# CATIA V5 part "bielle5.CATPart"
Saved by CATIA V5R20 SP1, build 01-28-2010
Part number: bielle5
Bounding box of the stored display mesh (mm): x 1 to 9, y -99.99 to 272.465, z -199.995 to -22.535
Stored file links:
  C:\Users\Fabien-port\Desktop\test\bielle5.CATPart
  C:\Users\Fabien-port\Desktop\test\mecanisme_a_coulisseau.CATProduct
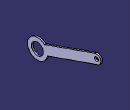
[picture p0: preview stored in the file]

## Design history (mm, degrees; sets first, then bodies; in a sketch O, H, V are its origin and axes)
External parameters (linked from other documents)
  External.largeur_bielle = 15 mm
  External.epaisseur_bielle = 8 mm
  External.cote_coulisseau = 30 mm
  External.grand_rayon_bielle5 = 50 mm
  External.rayon_cylindre_bielle = 10 mm
Set1
  Plane1 "Plan_decalage": linked copy from another document
  Point1 "Point_entraxe": linked copy from another document
  Point2 "PointB": linked copy from another document
Body1 (main body)
  Sketch1 on Plane1, origin (9, 0, 0), H (0, 1, 0), V (0, 0, 1)
    construction line L1 (-50, -150) -> (250, -45)
    point P1 (-50, -150)
    point P2 (250, -45)
    line L2 (-15.2883, -114.0126) -> (242.5671, -23.7632)
    line L3 (257.4329, -66.2368) -> (-0.4225, -156.4862)
    arc A1 centre (250, -45) radius 22.5 from (242.5671, -23.7632) to (257.4329, -66.2368) cw
    point P3 (-15.2883, -114.0126)
    reference projected point E1 (-50, -150) from Point1
    reference projected point E2 (250, -45) from Point2
    arc A2 centre (-50, -150) radius 50 from (-15.2883, -114.0126) to (-0.4225, -156.4862) ccw
    point P7 (-50, -150)
    point P8 (-97.1929, -166.5175)
    point P9 (-15.2883, -114.0126)
    reference projected point E3 (-50, -150) from Point1
    distance P1 E1 = 0
    distance P2 E2 = 0
    radius A1 = 22.5 {= 1.5*External.cote_coulisseau /2}
    angle L2 L1 = 0
    angle L1 L3 = 0
    distance P9 P3 = 0
    distance P7 E3 = 0
    radius A2 = 50 {= External.grand_rayon_bielle5}
    tangency: A1 L2, A1 L3
    coincidence: A2 P8, P8 L1
  Pad1: profile Sketch1, direction (-1, 0, 0), length 8 {= External.epaisseur_bielle}
  Sketch2 on start face of Pad1, origin (9, -50, -150), H (0, 1, 0), V (0, 0, 1)
    point P1 (0, 0)
    reference projected point E1 (0, 0) from Point1
    coincidence: E1 P1
  Hole1: placed by Sketch2, at (9, -50, -150) direction (-1, 0, 0), diameter 60 {= 2*3/5*External.grand_rayon_bielle5}, depth 8 {= External.epaisseur_bielle}
  Sketch3 on start face of Pad1, origin (9, 250, -45), H (0, 1, 0), V (0, 0, 1)
    point P1 (0, 0)
    reference projected point E1 (0, 0) from Point2
    coincidence: E1 P1
  Hole2: placed by Sketch3, at (9, 250, -45) direction (-1, 0, 0), diameter 20 {= External.rayon_cylindre_bielle *2}, depth 8 {= External.epaisseur_bielle}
